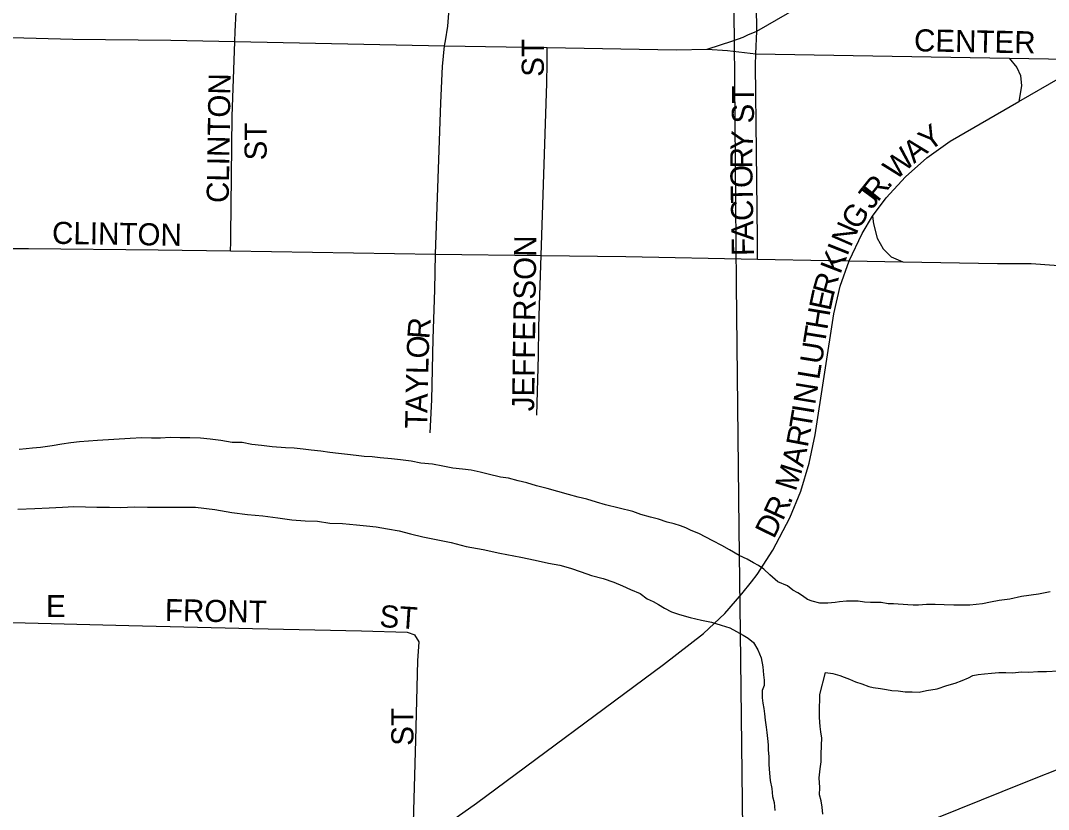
# Model space of a CAD drawing. Extents: x 1587405 to 1714697, y 1028970 to 1155083.
# Drawn here: x 1651141 to 1653466, y 1109170 to 1110955 of the extents above; entities that cross this region are included whole.
import ezdxf

# ---------------------------------------------------------------- set-up
doc = ezdxf.new("R2010")
doc.units = 0
for name, color, linetype in [('GM_X_City_Street', 7, 'Continuous'), ('GM_X_City_Street_Text', 7, 'Continuous'), ('GM_X_Major_River', 7, 'Continuous'), ('GM_X_Rail_Line', 7, 'Continuous'), ('GM_X_US_Route', 7, 'Continuous')]:
    doc.layers.add(name, color=color, linetype=linetype)

msp = doc.modelspace()

# ---------------------------------------------------------------- linework, layer by layer
at = {"layer": 'GM_X_City_Street'}
for points in [[(1651625.6, 1110907.9), (1651626.5, 1110930.7), (1651630.7, 1111018.9), (1651638.7, 1111329.3), (1651637.8, 1111397.8)], [(1652100, 1110898.3), (1652102.2, 1110909.6), (1652107.5, 1110942.5), (1652109.9, 1110971.9), (1652111.9, 1111186.3), (1652115.8, 1111389.2)], [(1652806.1, 1110931.3), (1652805.2, 1110989.5), (1652804.4, 1111035.9), (1652803.9, 1111066.2), (1652803.5, 1111277.9), (1652804.2, 1111377.1)], [(1652804.3, 1110880.4), (1652806.1, 1110931.3)], [(1651616.3, 1110434.1), (1651616.8, 1110453.9), (1651617.1, 1110468.9), (1651620.1, 1110738.5), (1651625.6, 1110907.9)], [(1652079.9, 1110426.5), (1652091.5, 1110769.3), (1652095.2, 1110851.2), (1652100, 1110898.3)], [(1652318.7, 1110423.5), (1652331, 1110813.8), (1652331.8, 1110859.1), (1652332.4, 1110894.5)], [(1652693.6, 1110890.9), (1652740, 1110887.3), (1652804.3, 1110880.4)], [(1652808, 1110415.6), (1652807.6, 1110461.4), (1652805.4, 1110658), (1652803.4, 1110854.3), (1652804.3, 1110880.4)], [(1652804.3, 1110880.4), (1653376.7, 1110870.4)], [(1653376.7, 1110870.4), (1653510.5, 1110868.1), (1653564, 1110867.4)], [(1653376.7, 1110870.4), (1653394.1, 1110849), (1653402.7, 1110830.7), (1653405.1, 1110807.6), (1653399, 1110772.4)], [(1653399, 1110772.4), (1653493.1, 1110826.7), (1653533, 1110850.5), (1653564, 1110867.4)], [(1653067.7, 1110512.4), (1653098.6, 1110553.9), (1653142.3, 1110601.7), (1653190.5, 1110644.9), (1653243.1, 1110682.5), (1653399, 1110772.4)], [(1653014.9, 1110411.6), (1653044.2, 1110473.9), (1653067.7, 1110512.4)], [(1653067.7, 1110512.4), (1653070.1, 1110495.1), (1653078.1, 1110463.3), (1653092.2, 1110438.8), (1653110.3, 1110420.8), (1653136.6, 1110409.3)], [(1651110.4, 1110439.9), (1651159.5, 1110439.4), (1651452.5, 1110436.8), (1651616.3, 1110434.1)], [(1651616.3, 1110434.1), (1652079.9, 1110426.5)], [(1652067.2, 1110022.9), (1652071.3, 1110096.9), (1652074.5, 1110235), (1652078.2, 1110345.8), (1652079.9, 1110426.5)], [(1652079.9, 1110426.5), (1652318.7, 1110423.5)], [(1652308.5, 1110062.3), (1652312.2, 1110197), (1652312.9, 1110261.9), (1652314.9, 1110311.2), (1652318.7, 1110423.5)], [(1652318.7, 1110423.5), (1652510.2, 1110421.2), (1652808, 1110415.6)], [(1652808, 1110415.6), (1652968.1, 1110412.5), (1653014.9, 1110411.6)], [(1652028, 1109082.5), (1652172, 1109184.9), (1652595.5, 1109498.3), (1652685.9, 1109568.7), (1652733.8, 1109613.6), (1652772.3, 1109658.6), (1652793.9, 1109685.4), (1652807.2, 1109702.2), (1652842.7, 1109757.4), (1652880.6, 1109830.2), (1652905.5, 1109890.8), (1652924.9, 1109953.6), (1652938.5, 1110017.7), (1652980.7, 1110291.6), (1652995, 1110354.6), (1653014.9, 1110411.6)], [(1653014.9, 1110411.6), (1653136.6, 1110409.3)], [(1653136.6, 1110409.3), (1653350.7, 1110405.4), (1653426.8, 1110405.4), (1653478.7, 1110402.2), (1653502.5, 1110399.6), (1653535.7, 1110393.5), (1653559.3, 1110390.1)], [(1651091.4, 1109594.3), (1651122.4, 1109593.5), (1651385.9, 1109587), (1651665.8, 1109580), (1651912.3, 1109574.5), (1652015.4, 1109571.4), (1652032.8, 1109565.5)], [(1652028, 1109082.5), (1652029, 1109114.5), (1652035.1, 1109326.9), (1652040, 1109506.6), (1652042.9, 1109549.6), (1652032.8, 1109565.5)], [(1652028, 1109082.5), (1652310.5, 1109075), (1652706.2, 1109064.5), (1652902.8, 1109055.6), (1652936, 1109055.8), (1652952.7, 1109057.2), (1652969.2, 1109059.9), (1652985.5, 1109063.6), (1653001.5, 1109068.2), (1653048.1, 1109085), (1653170.1, 1109134.2), (1653407.9, 1109230), (1653513.9, 1109272.3), (1653563.4, 1109292.9)]]:
    msp.add_lwpolyline(points, dxfattribs=at)
at = {"layer": 'GM_X_Major_River'}
for points in [[(1652583.7, 1109827.1), (1652565.7, 1109831.4), (1652543.8, 1109837.9), (1652525.8, 1109844.3), (1652463.9, 1109859.5), (1652444, 1109866), (1652422.1, 1109872.4), (1652402.1, 1109876.8), (1652380.1, 1109883.3), (1652356.2, 1109889.8), (1652332.2, 1109896.3), (1652308.3, 1109902.8), (1652286.4, 1109909.3), (1652266.4, 1109913.7), (1652244.4, 1109920.1), (1652226.4, 1109922.5), (1652198.5, 1109929.1), (1652180.5, 1109933.5), (1652160.5, 1109937.9), (1652140.5, 1109940.3), (1652118.5, 1109942.7), (1652096.5, 1109947.2), (1652072.5, 1109951.7), (1652046.5, 1109954.2), (1652024.5, 1109958.7), (1652000.5, 1109961.2), (1651980.4, 1109963.6), (1651954.4, 1109966.1), (1651936.4, 1109968.5), (1651918.3, 1109968.8), (1651900.3, 1109971.2), (1651880.3, 1109973.6), (1651860.3, 1109976), (1651840.3, 1109978.4), (1651820.3, 1109980.8), (1651798.2, 1109983.3), (1651780.2, 1109985.7), (1651760.2, 1109988.1), (1651740.2, 1109988.5), (1651710.1, 1109991.1), (1651686.1, 1109993.6), (1651664.1, 1109996), (1651642.1, 1110000.5), (1651620, 1110000.9), (1651594, 1110005.5), (1651570, 1110007.9), (1651548, 1110010.4), (1651523.9, 1110010.9), (1651501.8, 1110011.3), (1651479.8, 1110011.8), (1651457.7, 1110010.2), (1651437.6, 1110010.6), (1651415.5, 1110011.1), (1651389.4, 1110009.6), (1651315.1, 1110005.1), (1651295, 1110003.5), (1651274.9, 1110001.9), (1651254.8, 1110000.3), (1651234.6, 1109996.6), (1651212.5, 1109993.1), (1651186.3, 1109989.6), (1651168.2, 1109988), (1651154.2, 1109986.2), (1651138.1, 1109984.6)], [(1651135.4, 1109850.2), (1651173.5, 1109851.4), (1651205.6, 1109852.8), (1651235.8, 1109854.2), (1651261.9, 1109855.7), (1651288, 1109855.1), (1651314, 1109854.6), (1651342.1, 1109854.1), (1651368.2, 1109853.5), (1651398.3, 1109854.9), (1651428.4, 1109854.3), (1651536.8, 1109854.1), (1651580.8, 1109849.2), (1651618.8, 1109842.5), (1651654.8, 1109837.7), (1651688.9, 1109835.1), (1651722.9, 1109830.3), (1651754.9, 1109825.7), (1651784.9, 1109823.1), (1651813, 1109822.5), (1651841, 1109817.9), (1651869.1, 1109817.4), (1651901.2, 1109814.7), (1651923.2, 1109812.3), (1651945.2, 1109809.8), (1651971.2, 1109805.3), (1651997.2, 1109800.7), (1652023.2, 1109794.2), (1652051.1, 1109787.6), (1652081.1, 1109781), (1652115.1, 1109774.3), (1652149, 1109765.6), (1652187, 1109758.8), (1652224.9, 1109750), (1652272.9, 1109741)], [(1653469.3, 1109662.8), (1653443.1, 1109657.3), (1653404.8, 1109652), (1653378.7, 1109646.5), (1653354.5, 1109643), (1653334.4, 1109639.4), (1653316.2, 1109635.8), (1653302.1, 1109634), (1653288.1, 1109632.3), (1653272, 1109632.6), (1653252, 1109633), (1653229.9, 1109633.5), (1653209.8, 1109633.9), (1653189.8, 1109634.3), (1653171.7, 1109632.6), (1653159.7, 1109632.9), (1653147.6, 1109633.1), (1653115.6, 1109635.8), (1653103.5, 1109636), (1653087.5, 1109638.4), (1653063.5, 1109638.8), (1653049.4, 1109639.1), (1653035.4, 1109641.4), (1653023.4, 1109641.7), (1653009.3, 1109641.9), (1652993.3, 1109640.2), (1652983.2, 1109638.4), (1652967.1, 1109636.8), (1652949, 1109637.1), (1652931.1, 1109641.5), (1652921.1, 1109645.7), (1652909.3, 1109654), (1652899.3, 1109660.2), (1652887.4, 1109666.5), (1652875.6, 1109676.7), (1652853.7, 1109685.2), (1652836, 1109701.6), (1652822.2, 1109713.9), (1652810.3, 1109722.2), (1652798.4, 1109728.4), (1652784.5, 1109736.7), (1652766.6, 1109745.1), (1652744.8, 1109757.6), (1652727, 1109768), (1652707.1, 1109778.4), (1652691.2, 1109786.8), (1652675.3, 1109795.1), (1652657.4, 1109801.5), (1652645.5, 1109807.8), (1652633.5, 1109812), (1652619.6, 1109816.3), (1652603.6, 1109820.6), (1652583.7, 1109827.1)], [(1652272.9, 1109741), (1652304.9, 1109734.4), (1652334.8, 1109727.7), (1652360.8, 1109723.2), (1652384.8, 1109716.7), (1652408.7, 1109708.2), (1652432.6, 1109699.7), (1652458.5, 1109693.2), (1652482.5, 1109684.6), (1652502.4, 1109676.2), (1652520.2, 1109667.8), (1652542.1, 1109659.4), (1652557.9, 1109647), (1652571.9, 1109640.7), (1652583.8, 1109634.5), (1652597.7, 1109626.1), (1652613.5, 1109617.8), (1652631.5, 1109611.4), (1652655.4, 1109604.9), (1652681.4, 1109598.4), (1652703.4, 1109593.9), (1652725.3, 1109587.5), (1652745.2, 1109581.1), (1652775, 1109564.4), (1652786.9, 1109558.2), (1652798.7, 1109547.9), (1652808.4, 1109531.6), (1652816.1, 1109513.4), (1652819.7, 1109493.3), (1652821.3, 1109475.2), (1652823.1, 1109463.1), (1652822.9, 1109451.1), (1652818.6, 1109439.2), (1652818.3, 1109423.1), (1652820, 1109411.1), (1652821.8, 1109399), (1652823.6, 1109386.9), (1652825.3, 1109372.8), (1652827, 1109356.7), (1652828.7, 1109344.7), (1652830.4, 1109330.6), (1652832.2, 1109316.5), (1652831.9, 1109304.5), (1652833.6, 1109290.4), (1652833.3, 1109272.4), (1652834.9, 1109252.3), (1652836.5, 1109236.2), (1652840.2, 1109218.1), (1652841.8, 1109200), (1652845.6, 1109185.8), (1652847.2, 1109167.8)], [(1652955.4, 1109159.6), (1652953.7, 1109175.6), (1652952, 1109189.7), (1652948.3, 1109203.8), (1652948.6, 1109219.9), (1652947, 1109242), (1652949.4, 1109262), (1652951.8, 1109278), (1652952.1, 1109294), (1652952.6, 1109316.1), (1652952.9, 1109332.1), (1652951.2, 1109346.2), (1652949.4, 1109358.3), (1652947.8, 1109378.4), (1652948, 1109390.4), (1652948.3, 1109404.4), (1652948.6, 1109416.5), (1652948.9, 1109430.5), (1652961.9, 1109480.4), (1652977.9, 1109478.1), (1652993.9, 1109473.7), (1653003.8, 1109469.5), (1653015.8, 1109465.3), (1653029.7, 1109459), (1653043.7, 1109454.7), (1653059.6, 1109448.3), (1653069.6, 1109446.1), (1653085.6, 1109443.8), (1653099.6, 1109441.5), (1653111.6, 1109439.3), (1653125.6, 1109439), (1653141.6, 1109436.7), (1653157.7, 1109436.3), (1653173.7, 1109436), (1653189.8, 1109439.7), (1653214, 1109443.2), (1653236.2, 1109450.8), (1653254.4, 1109456.5), (1653270.6, 1109462.1), (1653284.7, 1109467.9), (1653294.9, 1109473.7), (1653307, 1109475.5), (1653321, 1109477.2), (1653337.1, 1109478.9)], [(1653337.1, 1109478.9), (1653353.2, 1109480.6), (1653369.3, 1109480.2), (1653383.3, 1109479.9), (1653405.4, 1109481.5), (1653421.5, 1109481.2), (1653441.5, 1109482.8), (1653461.6, 1109482.4), (1653487.7, 1109483.8)]]:
    msp.add_lwpolyline(points, dxfattribs=at)
at = {"layer": 'GM_X_Rail_Line'}
for points in [[(1652755.8, 1110909.9), (1652751.7, 1111190.9), (1652747.1, 1111407.1), (1652744, 1111475.6), (1652736.9, 1111545.6), (1652727.7, 1111599.3), (1652711.3, 1111669.8), (1652689.4, 1111740.8), (1652669.9, 1111801.1), (1652548.3, 1112173.7)], [(1653251, 1105641.9), (1653242.5, 1105747.1), (1653220.2, 1105951.3), (1653165.1, 1106461.2), (1653126.3, 1106804), (1653115.1, 1106882.7), (1653101.8, 1106965.5), (1653085.4, 1107051.9), (1653059.9, 1107163.3), (1653017.5, 1107326.8), (1652944.4, 1107604.8), (1652902, 1107765.3), (1652863.1, 1107918.1), (1652850.9, 1107980.5), (1652838.6, 1108075.5), (1652828.9, 1108191.5), (1652823.8, 1108291.7), (1652799.8, 1108641.3), (1652775.2, 1109061.4), (1652769.1, 1109570.9), (1652766.5, 1109806.5), (1652759.9, 1110358.4), (1652755.8, 1110909.9)]]:
    msp.add_lwpolyline(points, dxfattribs=at)
at = {"layer": 'GM_X_US_Route'}
for points in [[(1652786.2, 1110922.7), (1652806.1, 1110931.3), (1653380.9, 1111263.4), (1653538.2, 1111350.6), (1653566.9, 1111365.7), (1653786, 1111478.4), (1653826.7, 1111500.3), (1653901.6, 1111540.6), (1654033.6, 1111606.9), (1654260.3, 1111714.9), (1654285.4, 1111726.8), (1654301.4, 1111734.4), (1654537.6, 1111845.7), (1654628.2, 1111884.7), (1654678.6, 1111906.4), (1654735.4, 1111926), (1654889.9, 1111981.1), (1655029.8, 1112030.7), (1655503.9, 1112198.8), (1655783.6, 1112299.5), (1655903.7, 1112344.5), (1655981.2, 1112373.5), (1656147.8, 1112432.6), (1656236, 1112463.6)], [(1651121.1, 1110916.9), (1651259.2, 1110913.3), (1651481, 1110910.7), (1651625.6, 1110907.9), (1652100, 1110898.3), (1652332.4, 1110894.5), (1652624.1, 1110888.9), (1652693.6, 1110890.9), (1652751.6, 1110909.2), (1652775.2, 1110917.9), (1652786.2, 1110922.7)]]:
    msp.add_lwpolyline(points, dxfattribs=at)

# ---------------------------------------------------------------- texts
at = {"layer": 'GM_X_City_Street_Text'}
for s, rotation, p in [('CENTER', 358.9397, (1653161.4, 1110885.9)), ('ST', 90, (1652324.6, 1110828.1)), ('CLINTON', 89.0613, (1651611.8, 1110542.2)), ('ST', 90, (1652799.8, 1110722.5)), ('ST', 90, (1651697.8, 1110638.9)), ('Y', 36.5945, (1653195.7, 1110657.7)), ('Y', 86.0841, (1652796.2, 1110659.5)), ('W', 43.1095, (1653120.7, 1110592.2)), ('A', 38.4482, (1653161.6, 1110630.6)), ('R', 89.83, (1652796.2, 1110620.8)), ('O', 91.0492, (1652797, 1110577.1)), ('R', 51.3326, (1653079.6, 1110543)), ('T', 91.0497, (1652797.6, 1110541.9)), ('J', 53.4711, (1653066.8, 1110525.7)), ('.', 49.1223, (1653104, 1110573.6)), ('C', 91.0443, (1652798.3, 1110502.3)), ('G', 56.5949, (1653035.1, 1110479)), ('CLINTON', 359.0613, (1651212.1, 1110450.3)), ('A', 91.0521, (1652799.1, 1110458.3)), ('N', 66.3393, (1653018.6, 1110440.7)), ('JEFFERSON', 89.2352, (1652302.6, 1110071.1)), ('F', 91.0382, (1652799.8, 1110423.1)), ('I', 68.2879, (1653010.6, 1110420.6)), ('K', 68.8966, (1652994.8, 1110379.7)), ('R', 74.0613, (1652979.7, 1110330.4)), ('E', 78.0255, (1652972.6, 1110296.8)), ('H', 80.4478, (1652965.4, 1110254)), ('R', 85.5752, (1652065.4, 1110233.5)), ('T', 80.7532, (1652959.8, 1110219.3)), ('O', 88.2074, (1652064.1, 1110190.1)), ('U', 80.7735, (1652952.8, 1110175.9)), ('L', 88.7514, (1652063.3, 1110155.1)), ('L', 80.7532, (1652947.1, 1110141.1)), ('Y', 88.7104, (1652062.3, 1110111.1)), ('N', 80.7511, (1652937.9, 1110084.7)), ('A', 88.7323, (1652061.3, 1110067.1)), ('T', 88.7433, (1652060.6, 1110031.9)), ('T', 80.5979, (1652928.6, 1110028.1)), ('I', 80.7206, (1652934.4, 1110062.9)), ('R', 79.3305, (1652921.1, 1109988)), ('A', 77.0525, (1652910.8, 1109943)), ('M', 72.6441, (1652893.9, 1109888.5)), ('R', 65.4428, (1652865, 1109821.7)), ('.', 67.1904, (1652882.1, 1109859.2)), ('D', 63.7379, (1652844.8, 1109780.8)), ('E', 0, (1651198.8, 1109605.5)), ('FRONT', 358.9775, (1651467.3, 1109596.7)), ('ST', 356.1879, (1651951.8, 1109583.5)), ('ST', 90, (1652029.8, 1109314.5))]:
    msp.add_text(s, height=50, rotation=rotation, dxfattribs=at).set_placement(p)

doc.saveas('drawing.dxf')
